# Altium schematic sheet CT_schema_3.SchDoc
size 236 x 258 mm
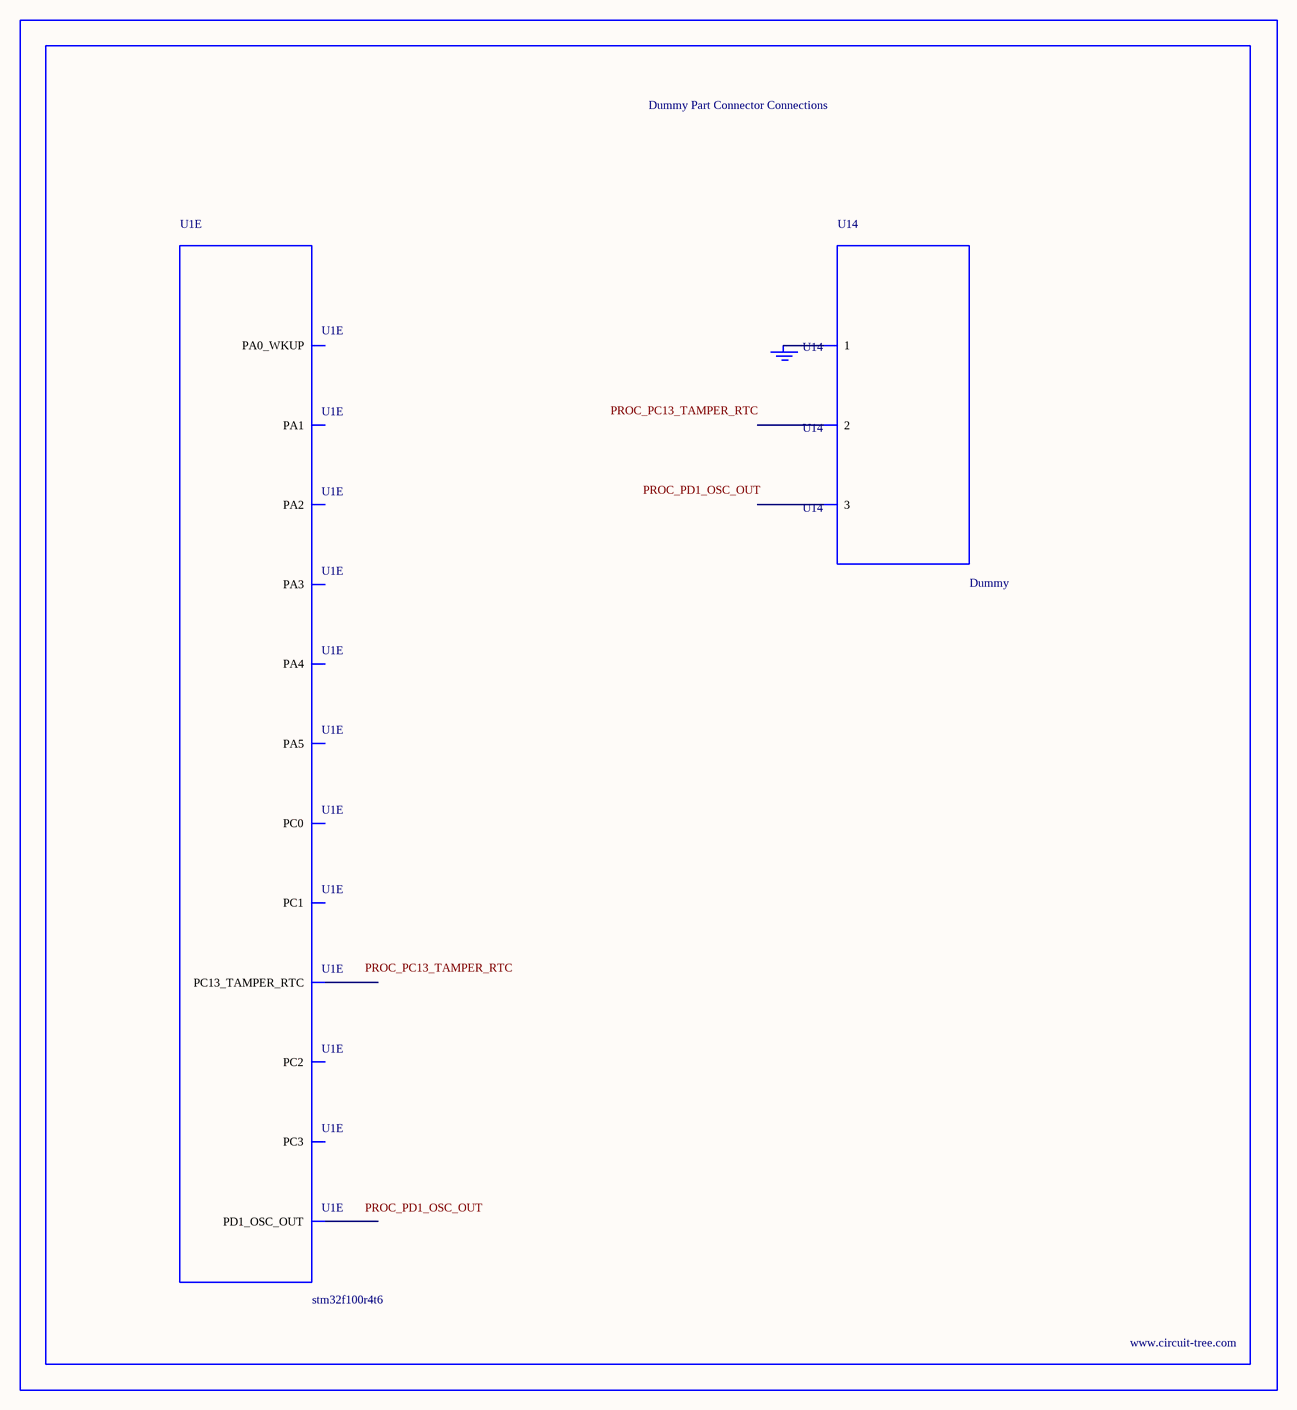
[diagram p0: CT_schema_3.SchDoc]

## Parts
BORDER2  (no value)
GND_INSTANCE_2_0  (no value)
U1  stm32f100r4t6  [LQFP64]  (part E of 5)
U14  Dummy  [DUMMY_PACKAGE_113]

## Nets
NetGND_INSTANCE_2_0_0: GND_INSTANCE_2_0.0(GND) U14.1

Not connected (* = marked no-connect by the designer): U1 2(PC13_TAMPER_RTC) 6(PD1_OSC_OUT) 8(PC0) 9(PC1) 10(PC2) 11(PC3) 14(PA0_WKUP) 15(PA1) 16(PA2) 17(PA3) 20(PA4) 21(PA5); U14 2 3

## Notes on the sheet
- Labels drawn without touching a wire or pin: PROC_PC13_TAMPER_RTC, PROC_PD1_OSC_OUT

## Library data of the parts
BORDER2 = BORDER_PAGE2
GND_INSTANCE_2_0 = GND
